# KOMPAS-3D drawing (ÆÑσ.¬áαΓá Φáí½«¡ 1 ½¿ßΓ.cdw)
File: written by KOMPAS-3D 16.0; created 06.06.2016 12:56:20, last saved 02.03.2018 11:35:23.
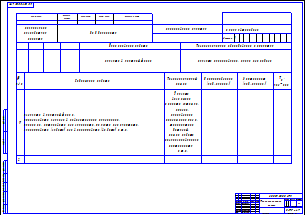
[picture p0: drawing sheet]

Sheet 1: A1, landscape

Title block, sheet 1: name: Технологическая / карта; designation: ДП 009.00.00 4ТЧ; scale: 1:1; sheets: 1; organisation: САТК - 47; sheet format: A1; revision letter: Д; stored path: C:\Documents and Settings\Admin\Мои документы\Мои рисунки\Базылев опер ката.cdw; drawn by: Ковалёв Р.С.; checked by: Ершов М.В.; standards control: Бервинова Н.К.; approved by: Ященко М.К.

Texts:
  Базылев опер карта
  satk
  Normal
  heading 1
  Стили документа
Dimensions and other numbers on the sheet: 1:1; 1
